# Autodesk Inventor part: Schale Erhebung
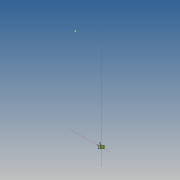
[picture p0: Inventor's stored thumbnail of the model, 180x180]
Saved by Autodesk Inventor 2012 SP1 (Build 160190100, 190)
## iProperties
Created: 2012-02
Part Number: Schale Erhebung
Material: S235JR+N ; 1.0116
Document SubType Name: Modeling
Designer: HUS
Density: 7.85 g/cm^3
Author: HUS
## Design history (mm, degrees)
workplane "Arbeitsebene1"
sketch "Skizze15"
  geometry: L1 (0, 112460.081)-(0, -18764.062) reference; L2 (-9727.778, 0)-(33842.875, 0) reference; L3 (233.258, 0)-(0, 0); L4 (-59.793, 88.26)-(221.355, 120.824); A1 r 97611.323 centre (27618.496, 93713.775) between (-29.671, 99.945) and (-29.671, 99.945); A2 r 1092.429 centre (-510.057, 901.526) between (582.372, 902.855) and (565.345, 1093.654); A3 r 72.871 centre (564.126, 1020.793) between (565.345, 1093.654) and (534.585, 1087.408); A4 r 2333.592 centre (-1751.218, 900.016) between (525.168, 386.483) and (582.372, 902.855); A5 r 2202.735 centre (-1667.311, 1026.612) between (397.261, 258.767) and (534.585, 1087.408); A6 r 276.67 centre (137.046, 355.352) between (379.784, 222.596) and (381.8, 226.351); A7 r 830.227 centre (-284.708, 569.184) between (382.626, 75.278) and (525.168, 386.483); A8 r 213.94 centre (196.739, 333.344) between (221.355, 120.824) and (397.261, 258.767); A9 r 185.828 centre (233.258, 185.828) between (233.258, 0) and (382.626, 75.278); A10 r 30 centre (-56.341, 58.459) between (-59.793, 88.26) and (-80.488, 40.656); A11 r 100 centre (0, 100) between (-80.488, 40.656) and (0, 0)
  constraints: 23 point on circle, 11 centre point, 9 tangent, 4 end point, 1 horizontal
  dimensions: "d197" = 100 radius of A11; "d198" = 30 radius of A10
sketch "Skizze16"
  geometry: L1 (233.259, 0)-(0, 0); L2 (-65.624, 24.545)-(-53.83, 36.782); L3 (-45.086, 70.419)-(238.074, 70.419); L4 (238.074, 70.419)-(238.074, 95.092); L5 (398.936, 202.433)-(418.507, 199.342); L6 (549.625, 827.221)-(534.585, 829.597); L7 (0, 0)-(233.259, 0); A1 r 1092.429 centre (-510.056, 901.526) between (582.372, 902.855) and (565.345, 1093.654); A2 r 72.871 centre (564.126, 1020.793) between (565.345, 1093.654) and (534.585, 1087.408); A3 r 17.417 centre (-48.326, 53.306) between (-45.086, 70.419) and (-53.83, 36.782); A4 r 194.102 centre (225.088, 288.759) between (238.074, 95.092) and (398.936, 202.433); A5 r 4086.087 centre (-3503.399, 1345.971) between (418.507, 199.342) and (549.625, 827.221); A6 r 2237.23 centre (-1698.928, 958.502) between (534.585, 829.597) and (534.585, 1087.408); A7 r 72.871 centre (564.126, 1020.793) between (549.625, 1092.207) and (534.585, 1087.408); A8 r 72.871 centre (564.126, 1020.793) between (565.345, 1093.654) and (549.625, 1092.207); A9 r 1092.429 centre (-510.056, 901.526) between (582.372, 902.855) and (565.345, 1093.654); A10 r 2333.592 centre (-1751.218, 900.016) between (525.168, 386.483) and (582.372, 902.855); A11 r 100 centre (0, 100) between (-65.624, 24.545) and (0, 0); A12 r 830.227 centre (-284.707, 569.184) between (382.627, 75.278) and (525.168, 386.483); A13 r 830.227 centre (-284.707, 569.184) between (382.627, 75.278) and (525.168, 386.483); A14 r 185.828 centre (233.258, 185.828) between (233.259, 0) and (382.627, 75.278)
  constraints: 29 point on circle, 14 centre point, 14 end point, 2 concentric, 2 parallel, 2 perpendicular, 2 tangent
sketch "Skizze19"
  geometry: L1 (-39.856, 70.419)-(-250, 70.419); A1 r 44.178 centre (-39.856, 114.598) between (-39.856, 70.419) and (-0.105, 95.321)
  constraints: 2 end point, 2 point on circle, 1 centre point, 1 horizontal, 1 tangent
chamfer "Fase3" distance "d159" = 180; stored, may be unused: second distance "d160" = 2, angle "d161" = 30 deg
sketch "Skizze17"
  geometry: L1 (0, -2052.565)-(-250, -2052.565) reference; L2 (0, -2052.565)-(0, -2059.738) reference; L3 (0, -2850.001)-(0, -2059.738) reference; L4 (0, -2052.565)-(0, -2302.565); L5 (-167.543, -2052.565)-(0, -2052.565); L6 (-72.505, -2256.375)-(-167.543, -2052.565); L7 (0, -2302.565)-(21.782, -2302.565); A1 r 80 centre (0, -2222.565) between (-72.505, -2256.375) and (0, -2302.565); 3 further points
  constraints: 8 end point, 3 point on line, 2 point on circle, 2 tangent, 1 centre point, 1 collinear, 1 parallel
  dimensions: "d170" = 250 distance between parallel lines of L7 L1; "d171" = 80 radius of A1; "d172" = 65 deg angle of L7 L6
extrude "Extrusion11" cut sketch "Skizze17" stored distance "d165" = 0; taper "d166" = 0 deg
mirror "Spiegeln3"
node "Volumenkörper3"
node "Volumenkörpern"
node "Oberflächenkörpern"
node "Volumenkörper7"
